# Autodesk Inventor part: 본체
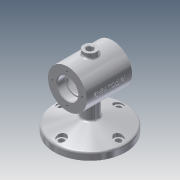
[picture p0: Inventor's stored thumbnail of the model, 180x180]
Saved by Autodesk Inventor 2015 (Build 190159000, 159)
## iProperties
Created: 2018-12
Part Number: 본체
Material: 알루미늄 6061
Document SubType Name: Modeling
Designer: now
Density: 2.7 g/cm^3
Appearance: 알루미늄 - 평지
Mass: 684.769 g
Surface Area: 556.949 cm^2
Volume: 253.618 cm^3
Author: now
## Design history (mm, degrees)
sketch "스케치1"
  geometry: C1 r 30 at (0, 0); 1 further point
  constraints: 1 centre point, 1 coincident
  dimensions: "d0" = 60 diameter of C1
extrude "돌출1" new body sketch "스케치1" stored distance "d1" = 70; taper "d2" = 0 deg
sketch "스케치2"
  geometry: L1 (-35, -30)-(-35, 30) reference; L2 (-35, 30)-(35, 30) reference; L3 (35, 30)-(35, -30) reference; L4 (35, -30)-(-35, -30) reference; L5 (-35, 0)-(-23, 0); L6 (-23, 0)-(-23, 15.7); L7 (-23.3, 16)-(-35, 16); L8 (-35, 16)-(-35, 0); L9 (-23, 0)-(-20, 0); L10 (-20, 0)-(-20, 14); L11 (-20, 14)-(-23, 14); L12 (-23, 14)-(-23, 0); L13 (-20, 0)-(20, 0); L14 (20, 0)-(20, 22); L15 (17, 25)-(-17, 25); L16 (-20, 22)-(-20, 0); L17 (20, 0)-(23, 0); L18 (23, 0)-(23, 14); L19 (23, 14)-(20, 14); L20 (20, 14)-(20, 0); L21 (35, -30)-(35, 30) reference; L22 (23, 0)-(35, 0); L23 (35, 0)-(35, 16); L24 (35, 16)-(23.3, 16); L25 (23, 15.7)-(23, 0); A1 r 3 centre (-17, 22) between (-17, 25) and (-20, 22); A2 r 3 centre (17, 22) between (20, 22) and (17, 25); A3 r 0.3 centre (-23.3, 15.7) between (-23, 15.7) and (-23.3, 16); A4 r 0.3 centre (23.3, 15.7) between (23.3, 16) and (23, 15.7); 1 further point
  constraints: 40 end point, 10 parallel, 8 point on circle, 8 tangent, 5 horizontal, 5 perpendicular, 4 centre point, 2 equal radius, 1 midpoint, 1 point on line
  dimensions: "d3" = 16 distance between parallel lines of L5 L7; "d4" = 12 distance between parallel lines of L1 L6; "d5" = 14 distance between parallel lines of L9 L11; "d6" = 40 distance between parallel lines of L14 L16; "d7" = 25 distance between parallel lines of L13 L15; "d8" = 3 distance between parallel lines of L10 L12; "d9" = 3 distance between parallel lines of L20 L18; "d10" = 14 distance between parallel lines of L19 L17; "d11" = 16 distance between parallel lines of L22 L24; "d12" = 3 radius of A1; "d13" = 0.3 radius of A3
revolve "회전1" sketch "스케치2" stored, may be unused: angle "d14" = 90 deg
chamfer "모따기1" distance "d15" = 1; stored, may be unused: second distance "d16" = 2, angle "d17" = 45 deg
sketch "스케치3" dims "d18" = 46
  geometry: C1 r 30 at (0, 0) reference; C2 r 17 at (0, 0) reference; 2 further points
  constraints: 2 vertical alignment, 1 coincident, 2 other
hole "구멍1" sketch "스케치3" at (0, 23) diameter "d19" = 3.242; stored, may be unused: countersink angle "d23" = 90 deg, drill point angle "d25" = 118 deg; dims "d20" = 8, "d21" = 4, "d22" = 2, "d24" = 10
node "작업 평면1"
sketch "스케치4"
  geometry: C1 r 55 at (0, 0); 1 further point
  constraints: 1 centre point, 1 coincident
  dimensions: "d30" = 110 diameter of C1
extrude "돌출2" join sketch "스케치4" distance "d31" = 11; taper "d32" = 0 deg
sketch "스케치5"
  geometry: C1 r 55 at (0, 0) reference; C2 r 12 at (0, 0)
  constraints: 1 centre point, 1 coincident
  dimensions: "d33" = 24 diameter of C2
extrude "돌출3" join sketch "스케치5" stored distance "d34" = 10; taper "d35" = 0 deg
node "작업 평면2"
sketch "스케치6"
  geometry: C1 r 10 at (0, 0); 1 further point
  constraints: 1 centre point, 1 coincident
  dimensions: "d37" = 20 diameter of C1
extrude "돌출4" join sketch "스케치6" stored distance "d38" = 10; taper "d39" = 0 deg
sketch "스케치7"
  geometry: C1 r 10 at (0, 0) reference; C2 r 5 at (0, 0)
  constraints: 1 centre point, 1 coincident
  dimensions: "d40" = 10 diameter of C2
extrude "돌출5" cut sketch "스케치7" stored distance "d41" = 10; taper "d42" = 0 deg
chamfer "모따기2" distance "d43" = 1; stored, may be unused: second distance "d44" = 2, angle "d45" = 45 deg
fillet "모깎기1" dims "d46" = 3
fillet "모깎기2" dims "d47" = 3
node "작업 평면3"
sketch "스케치8"
  geometry: L1 (-10, 37)-(10, 37) reference; L2 (-35, 30)-(-35, -30) reference; L3 (39.999, -75)-(-39.999, -75) reference; L4 (-39.999, -75)-(-39.999, -64) reference; L5 (-39.999, -64)-(39.999, -64) reference; L6 (39.999, -64)-(39.999, -75) reference; 2 further points
  constraints: 1 other
  dimensions: "d52" = 0 distance of point (0, 0) point (0, 0); "d69" = 30 vertical distance of L2.start point (0, 0); "d70" = 35 horizontal distance of L2.start point (0, 0)
feature "엠보싱1" sketch "스케치8" dims "d3" = 16, "d4" = 12, "d5" = 14, "d6" = 40, "d7" = 25, "d8" = 3, "d9" = 3, "d10" = 14, "d11" = 16, "d12" = 3, "d13" = 0.3, "d53" = 0.5, "d54" = 0
sketch "스케치9"
  geometry: L1 (-23, 14)-(-23, 15.7) reference; L2 (-23.3, 16)-(-34, 16) reference; L3 (-34, 16)-(-35, 17) reference; L4 (-35, 17)-(-35, 21.379) reference; L5 (-35, 21.379)-(-25, 21.379) reference; L6 (-25, 21.379)-(-24.026, 23) reference; L7 (-24.026, 23)-(-25, 24.621) reference; L8 (-25, 24.621)-(-35, 24.621) reference; L9 (-35, 24.621)-(-35, 30) reference; L10 (-35, 30)-(-13, 30) reference; L11 (-10, 33)-(-10, 37) reference; L12 (-10, 37)-(-6, 37) reference; L13 (-6, 37)-(-5, 36) reference; L14 (-5, 36)-(-5, 25) reference; L15 (-5, 25)-(-17, 25) reference; L16 (-20, 22)-(-20, 14) reference; L17 (-20, 14)-(-23, 14) reference; L18 (23, 15.7)-(23, 14) reference; L19 (23, 14)-(20, 14) reference; L20 (20, 14)-(20, 22) reference; L21 (17, 25)-(5, 25) reference; L22 (5, 25)-(5, 36) reference; L23 (5, 36)-(6, 37) reference; L24 (6, 37)-(10, 37) reference; L25 (10, 37)-(10, 33) reference; L26 (13, 30)-(35, 30) reference; L27 (35, 30)-(35, 24.621) reference; L28 (35, 24.621)-(25, 24.621) reference; L29 (25, 24.621)-(24.026, 23) reference; L30 (24.026, 23)-(25, 21.379) reference; L31 (25, 21.379)-(35, 21.379) reference; L32 (35, 21.379)-(35, 17) reference; L33 (35, 17)-(34, 16) reference; L34 (34, 16)-(23.3, 16) reference; L35 (23, -14)-(23, -15.7) reference; L36 (23.3, -16)-(34, -16) reference; L37 (34, -16)-(35, -17) reference; L38 (35, -17)-(35, -21.379) reference; L39 (35, -21.379)-(25, -21.379) reference; L40 (25, -21.379)-(24.026, -23) reference; L41 (24.026, -23)-(25, -24.621) reference; L42 (25, -24.621)-(35, -24.621) reference; L43 (35, -24.621)-(35, -30) reference; L44 (35, -30)-(15, -30) reference; L45 (12, -33)-(12, -64) reference; L46 (12, -64)-(55, -64) reference; L47 (55, -64)-(55, -75) reference; L48 (55, -75)-(-55, -75) reference; L49 (-55, -75)-(-55, -64) reference; L50 (-55, -64)-(-12, -64) reference; L51 (-12, -64)-(-12, -33) reference; L52 (-15, -30)-(-35, -30) reference; L53 (-35, -30)-(-35, -24.621) reference; L54 (-35, -24.621)-(-25, -24.621) reference; L55 (-25, -24.621)-(-24.026, -23) reference; L56 (-24.026, -23)-(-25, -21.379) reference; L57 (-25, -21.379)-(-35, -21.379) reference; L58 (-35, -21.379)-(-35, -17) reference; L59 (-35, -17)-(-34, -16) reference; L60 (-34, -16)-(-23.3, -16) reference; L61 (-23, -15.7)-(-23, -14) reference; L62 (-23, -14)-(-20, -14) reference; L63 (-20, -14)-(-20, -22) reference; L64 (-17, -25)-(17, -25) reference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; A1 r 0.3 centre (-23.3, 15.7) between (-23, 15.7) and (-23.3, 16) reference; A2 r 3 centre (-17, 22) between (-17, 25) and (-20, 22) reference; A3 r 3 centre (17, 22) between (20, 22) and (17, 25) reference; A4 r 0.3 centre (23.3, 15.7) between (23.3, 16) and (23, 15.7) reference; A5 r 0.3 centre (23.3, -15.7) between (23, -15.7) and (23.3, -16) reference; A6 r 0.3 centre (-23.3, -15.7) between (-23.3, -16) and (-23, -15.7) reference; A7 r 3 centre (-17, -22) between (-20, -22) and (-17, -25) reference; A8 r 3 centre (17, -22) between (17, -25) and (20, -22) reference; 1 further point
  constraints: 6 end point, 1 midpoint, 1 vertical, 4 other
  dimensions: "d55" = 75 deg angle of L67 L49
revolve "회전2" sketch "스케치9" stored, may be unused: angle "d56" = 90 deg
fillet "모깎기3" dims "d57" = 3
sketch "스케치10" dims "d58" = 88
  geometry: C1 r 55 at (0, 0) reference; C2 r 4.5 at (-44, 0); 1 further point
  constraints: 1 centre point, 1 coincident, 1 horizontal alignment, 2 other
  dimensions: "d59" = 9 diameter of C2
extrude "돌출6" cut sketch "스케치10" distance "d60" = 10; taper "d61" = 0 deg
sketch "스케치11"
  geometry: C1 r 4.5 at (0, 0) reference; C2 r 7 at (0, 0); 1 further point
  constraints: 1 centre point, 1 coincident
  dimensions: "d62" = 14 diameter of C2
extrude "돌출7" cut sketch "스케치11" distance "d63" = 10; taper "d64" = 0 deg
fillet "모깎기4" dims "d68" = 3
node "솔리드1"
pattern_circular "원형 패턴1" dims angle "d27" = 360 deg
mirror "대칭1"
pattern_circular "원형 패턴2" dims angle "d66" = 360 deg
node "절단 모서리 투영1"
node "절단 모서리 투영2"
node "절단 모서리 투영3"
other parameters: "d29" = -75, "d36" = 37, "d48" = 37.75
